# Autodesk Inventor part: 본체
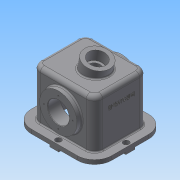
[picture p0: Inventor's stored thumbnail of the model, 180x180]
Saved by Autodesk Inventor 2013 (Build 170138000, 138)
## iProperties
Created: 2014-11
Part Number: 본체
Material: 일반
Document SubType Name: Modeling
Designer: Administrator
Density: 1 g/cm^3
Author: Administrator
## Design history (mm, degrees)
sketch "스케치1"
  geometry: L1 (-76, -65)-(76, -65); L2 (76, -65)-(76, 65); L3 (76, 65)-(-76, 65); L4 (-76, 65)-(-76, -65); L5 (-76, -65)-(76, 65); L6 (76, -65)-(-76, 65); L7 (-98, -87)-(98, -87); L8 (98, -87)-(98, 87); L9 (98, 87)-(-98, 87); L10 (-98, 87)-(-98, -87); L11 (-98, -87)-(98, 87); L12 (98, -87)-(-98, 87); 1 further point
  constraints: 24 end point, 4 midpoint, 4 parallel, 2 horizontal, 2 perpendicular
  dimensions: "d0" = 152 distance of L3.end L2.end; "d1" = 130 distance of L2.end L1.end; "d2" = 196 distance of L9.end L8.end; "d3" = 174 distance of L8.end L7.end
extrude "돌출1" new body sketch "스케치1" distance "d4" = 128; taper "d5" = 0 deg
sketch "스케치2"
  geometry: L1 (76, 128)-(-76, 128) reference; L2 (-98, 0)-(98, 0) reference; L3 (0, 68)-(-17.88, 152.121); L4 (0, 68)-(-62.657, 68); L5 (12.442, 158.566)-(20.759, 119.44); L6 (12.442, 158.566)-(-17.88, 152.121); L7 (20.759, 119.44)-(-9.564, 112.995); C1 r 45.5 at (0, 68); 2 further points
  constraints: 10 end point, 2 parallel, 1 centre point, 1 midpoint, 1 perpendicular, 1 point on line, 1 vertical alignment
  dimensions: "d6" = 91 diameter of C1; "d7" = 68 distance from line of L3.start L2; "d13" = 78 deg angle of L3 L4; "d14" = 86 distance of L3.end L3.start; "d15" = 62 diameter of L5 L3; "d67" = 40 distance between parallel lines of L7 L6
extrude "돌출2" join sketch "스케치2" stored distance "d8" = 154; taper "d9" = 0 deg
extrude "돌출3" join sketch "스케치1" distance "d11" = 10; taper "d12" = 0 deg
revolve "회전1" stored, may be unused: angle "d20" = 90 deg
sketch "스케치3"
  geometry: L1 (-76, 10)-(-76, 128) reference; L2 (76, 10)-(76, 128) reference; L3 (66, 0)-(66, 118); L4 (76, 128)-(-76, 128) reference; L5 (66, 118)-(-66, 118); L6 (-66, 0)-(-66, 118); L7 (-98, 0)-(98, 0) reference
  constraints: 6 end point, 3 parallel, 2 point on line
  dimensions: "d21" = 10 distance between parallel lines of L4 L5; "d22" = 10 distance between parallel lines of L2 L3; "d23" = 10 distance between parallel lines of L1 L6
extrude "돌출4" cut sketch "스케치3" stored distance "d24" = 110; taper "d25" = 0 deg
sketch "스케치4" dims "d27" = 70
  geometry: C1 r 45.5 at (0, 0) reference; C2 r 26 at (0, 0); 3 further points
  constraints: 2 coincident, 2 vertical alignment, 1 centre point, 2 other
  dimensions: "d26" = 52 diameter of C2
hole "구멍1" sketch "스케치4" diameter "d28" = 3.242; stored, may be unused: countersink angle "d32" = 90 deg, drill point angle "d34" = 118 deg; dims "d29" = 13, "d30" = 4, "d31" = 2, "d33" = 16
node "작업 평면1"
sketch "스케치5"
  geometry: L1 (-66, -55)-(66, -55) reference; L2 (66, -55)-(66, 55) reference; L3 (66, 55)-(-66, 55) reference; L4 (-66, 55)-(-66, -55) reference; L5 (-98, -87)-(98, -87) reference; L6 (-98, 87)-(-98, -87) reference; L7 (98, 87)-(-98, 87) reference; L8 (98, -87)-(98, 87) reference; L9 (0, 55)-(0, 45); L10 (45.5, 55)-(35.5, 45); L11 (35.5, 45)-(0, 45); 1 further point
  constraints: 6 end point, 1 midpoint, 1 parallel, 1 perpendicular, 1 point on line
  dimensions: "d39" = 10 distance between parallel lines of L11 L3; "d40" = 91 diameter of L10.start L9; "d41" = 71 diameter of L10.end L9
revolve "회전2" sketch "스케치5" stored, may be unused: angle "d42" = 90 deg
extrude "돌출5" cut sketch "스케치4" stored distance "d43" = 110; taper "d44" = 0 deg
sketch "스케치6"
  geometry: L1 (98, -87)-(-98, -87) reference; L2 (98, 87)-(98, -87) reference; L3 (-98, 87)-(98, 87) reference; L4 (-98, -87)-(-98, 87) reference; L5 (-11, -67)-(11, -67); L6 (11, -67)-(11, -87); L7 (11, -87)-(-11, -87); L8 (-11, -87)-(-11, -67); L9 (78, 11)-(98, 11); L10 (98, 11)-(98, -11); L11 (98, -11)-(78, -11); L12 (78, -11)-(78, 11); L13 (-11, 87)-(11, 87); L14 (11, 87)-(11, 67); L15 (11, 67)-(-11, 67); L16 (-11, 67)-(-11, 87); L17 (-98, -11)-(-78, -11); L18 (-78, -11)-(-78, 11); L19 (-78, 11)-(-98, 11); L20 (-98, 11)-(-98, -11); 14 further points
  constraints: 32 end point, 13 midpoint, 8 parallel, 7 coincident, 4 horizontal, 4 perpendicular, 1 vertical alignment
  dimensions: "d45" = 22 distance of L5.start L5.end; "d47" = 20 distance of L5.end L6.end; "d48" = 20 distance of L9.start L9.end; "d49" = 22 distance of L11.end L9.start; "d50" = 20 distance of L13.end L14.end; "d51" = 22 distance of L14.end L15.end; "d52" = 20 distance of L18.end L19.end; "d53" = 22 distance of L17.end L18.end
extrude "돌출6" join sketch "스케치6" distance "d54" = 5; taper "d55" = 0 deg
sketch "스케치7"
  geometry: L1 (-98, -87)-(98, -87) reference; L2 (98, -87)-(98, 87) reference; L3 (98, 87)-(-98, 87) reference; L4 (-98, 87)-(-98, -87) reference; L5 (-98, 0)-(98, 0); L6 (0, 87)-(0, -87); 5 further points
  constraints: 4 end point, 4 midpoint, 4 point on line
  dimensions: "d56" = 10 distance from line of point (0, 77) L3; "d57" = 10 distance from line of L4 point (-88, 0); "d58" = 10 distance of L6.end point (0, -77); "d59" = 10 distance from line of L2 point (88, 0)
hole "구멍2" sketch "스케치7" at (0, 77), (-88, 0), (88, 0), (0, -77) diameter "d60" = 9; stored, may be unused: countersink angle "d64" = 90 deg, drill point angle "d66" = 118 deg; dims "d61" = 13, "d62" = 14, "d63" = 8.6, "d65" = 16
hole "구멍3" diameter "d70" = 30; stored, may be unused: countersink angle "d74" = 90 deg, drill point angle "d76" = 118 deg; dims "d68" = 10, "d69" = 10, "d71" = 13, "d72" = 42, "d73" = 25, "d75" = 16
fillet "모깎기1" dims "d77" = 42, "d78" = 20, "d79" = 10
fillet "모깎기2" dims "d80" = 10, "d81" = 3
fillet "모깎기3" dims "d82" = 0.3
chamfer "모따기1" distance "d83" = 1; stored, may be unused: second distance "d84" = 2, angle "d85" = 45 deg
sketch "스케치9"
  geometry: L1 (-105, 0)-(-105, 90) reference; L2 (13, 0)-(13, 34) reference; 3 further points
  constraints: 1 horizontal alignment, 1 midpoint, 1 other
  dimensions: "d86" = 92 distance from line of L2 point (-79, 45)
feature "엠보싱1" sketch "스케치9" dims "d0" = 152, "d1" = 130, "d87" = 1, "d88" = 0
node "솔리드1"
pattern_circular "원형 패턴1" dims angle "d36" = 360 deg
mirror "대칭1"
mirror "대칭2"
node "투영된 루프1"
other parameters: "d38" = -68
